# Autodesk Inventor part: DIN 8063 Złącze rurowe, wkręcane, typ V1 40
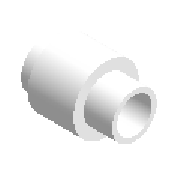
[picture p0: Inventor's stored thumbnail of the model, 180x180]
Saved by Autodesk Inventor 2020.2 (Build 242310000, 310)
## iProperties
Manager: www.cadconsulting.pl
Company: Fabian Stasiak CAD Consulting
NAME: PIPING: DIN 8063 Screwed Pipe Joint Type V1
DATA: <meta><inlinegroups number="1" deflen="4.1"></inlinegroups><connections number="2"></connections><angles><a>3.14159265358979</a></angles></meta>
Created: 2014-02
Part Number: DIN 8063 Złącze rurowe, wkręcane, typ V1 40
Material: PCW, nieplastyfikowany
Description: Dwuzłączka
Document SubType Name: Modeling
Standard: DIN 8063
Designer: F.Stasiak
Standards Organization: DIN
Language: pl-PL
Size Designation: 40
Categories: <MemberInstance><Categories><Category DisplayName="Rury cienko- i grubościenne" InternalName="4347fa0f-2144-441d-94cd-e3e15c92b736" Mnemonic="TUBEANDPIPE"><Cate
Density: 1.29 g/cm^3
Appearance: Gładki - biały
Catalog Web Link: www.expertbooks.pl
IsCustomPart: 0
Author: F.Stasiak
Subject: Zbiór ćwiczeń. Autodesk Inventor 2020. Kurs Professional
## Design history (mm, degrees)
sketch "Sketch1"
  geometry: L1 (0, 0)-(-67, 0); L2 (0, 0)-(0, 20); L3 (0, 20)-(-26, 20); L4 (-26, 20)-(-26, 16.5); L5 (-26, 16.5)-(-29, 16.5); L6 (-29, 16.5)-(-29, 21); L7 (-29, 21)-(-31, 21); L8 (-31, 21)-(-31, 16.5); L9 (-31, 16.5)-(-41, 16.5); L10 (-41, 16.5)-(-41, 20); L11 (-41, 20)-(-67, 20); L12 (-67, 20)-(-67, 24.875); L13 (-67, 24.875)-(-45, 24.875); L14 (-45, 24.875)-(-45, 34.75); L15 (-45, 34.75)-(-15, 34.75); L16 (-15, 34.75)-(-15, 26.5); L17 (-15, 26.5)-(0, 26.5); L18 (0, 26.5)-(0, 20); L19 (-67, 0)-(-67, 20); L20 (-26, 16.5)-(-26, 0); L21 (-41, 16.5)-(-41, 0); L22 (-29, 16.5)-(-31, 16.5); L23 (-26, 20)-(-41, 20)
  constraints: 46 end point, 10 parallel, 9 perpendicular, 3 collinear, 2 point on line, 1 horizontal
  dimensions: "d0" = 40 diameter of L3 L1 (= D1); "d1" = 33 diameter of L5 L1 (= D8); "d2" = 53 diameter of L17 L1 (= D3); "d5" = 42 diameter of L7 L1 (= D6); "d6" = 49.75 diameter of L13 L1 (= 0.75 x D3 + 0.25 x D1); "d7" = 69.5 diameter of L15 L1 (= D4 - D1 + D3); "d8" = 26 distance between parallel lines of L2 L20 (= t); "d9" = 2 distance between parallel lines of L6 L8 (= s1); "d10" = 14 distance between parallel lines of L8 L14 (= L1); "d11" = 30 distance between parallel lines of L14 L16 (= 2 x h1 + L1 + s1); "d12" = 3 distance between parallel lines of L20 L6 (= z1); "d13" = 10 distance between parallel lines of L8 L21 (= z2); "d14" = 26 distance between parallel lines of L21 L19 (= t)
revolve "Revolve1" sketch "Sketch1" stored, may be unused: angle "d18" = 90 deg
workaxis "Work Axis1"
workpoint "Work Point1"
workpoint "Work Point2"
workaxis "Work Axis2"
workpoint "Work Point3"
workpoint "Work Point4"
body "Solid1"
other parameters: "D1" = 40 [user parameter; used in 3 equation terms], "D3" = 53 [user parameter; used in 3 equation terms], "D4" = 56.5 [user parameter; used in 1 equation term], "D6" = 42 [user parameter; used in 1 equation term], "D8" = 33 [user parameter; used in 1 equation term], "t" = 26 [user parameter; used in 2 equation terms], "z1" = 3 [user parameter; used in 1 equation term], "z2" = 10 [user parameter; used in 1 equation term], "s1" = 2 [user parameter; used in 2 equation terms], "L1" = 14 [user parameter; used in 2 equation terms], "h1" = 7 [user parameter; used in 1 equation term]
